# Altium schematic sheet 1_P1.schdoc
size 309 x 223 mm; Symbol: Sheet-Symbol_A4; Device: Sheet-Symbol_A4; Company: ChisBread/ChisFlash-Prometheus; Drawed: ChisBread; Reviewed: ChisBread; Version: 2; Page Size: A4; @Project Name: GBA烧录卡; @Page Count: 1; @Update Date: 2024-08-13; @Create Date: 2024-08-13; @Schematic Name: ChisFlash-Prometheus_1; @Page No: 1; @Page Name: P1
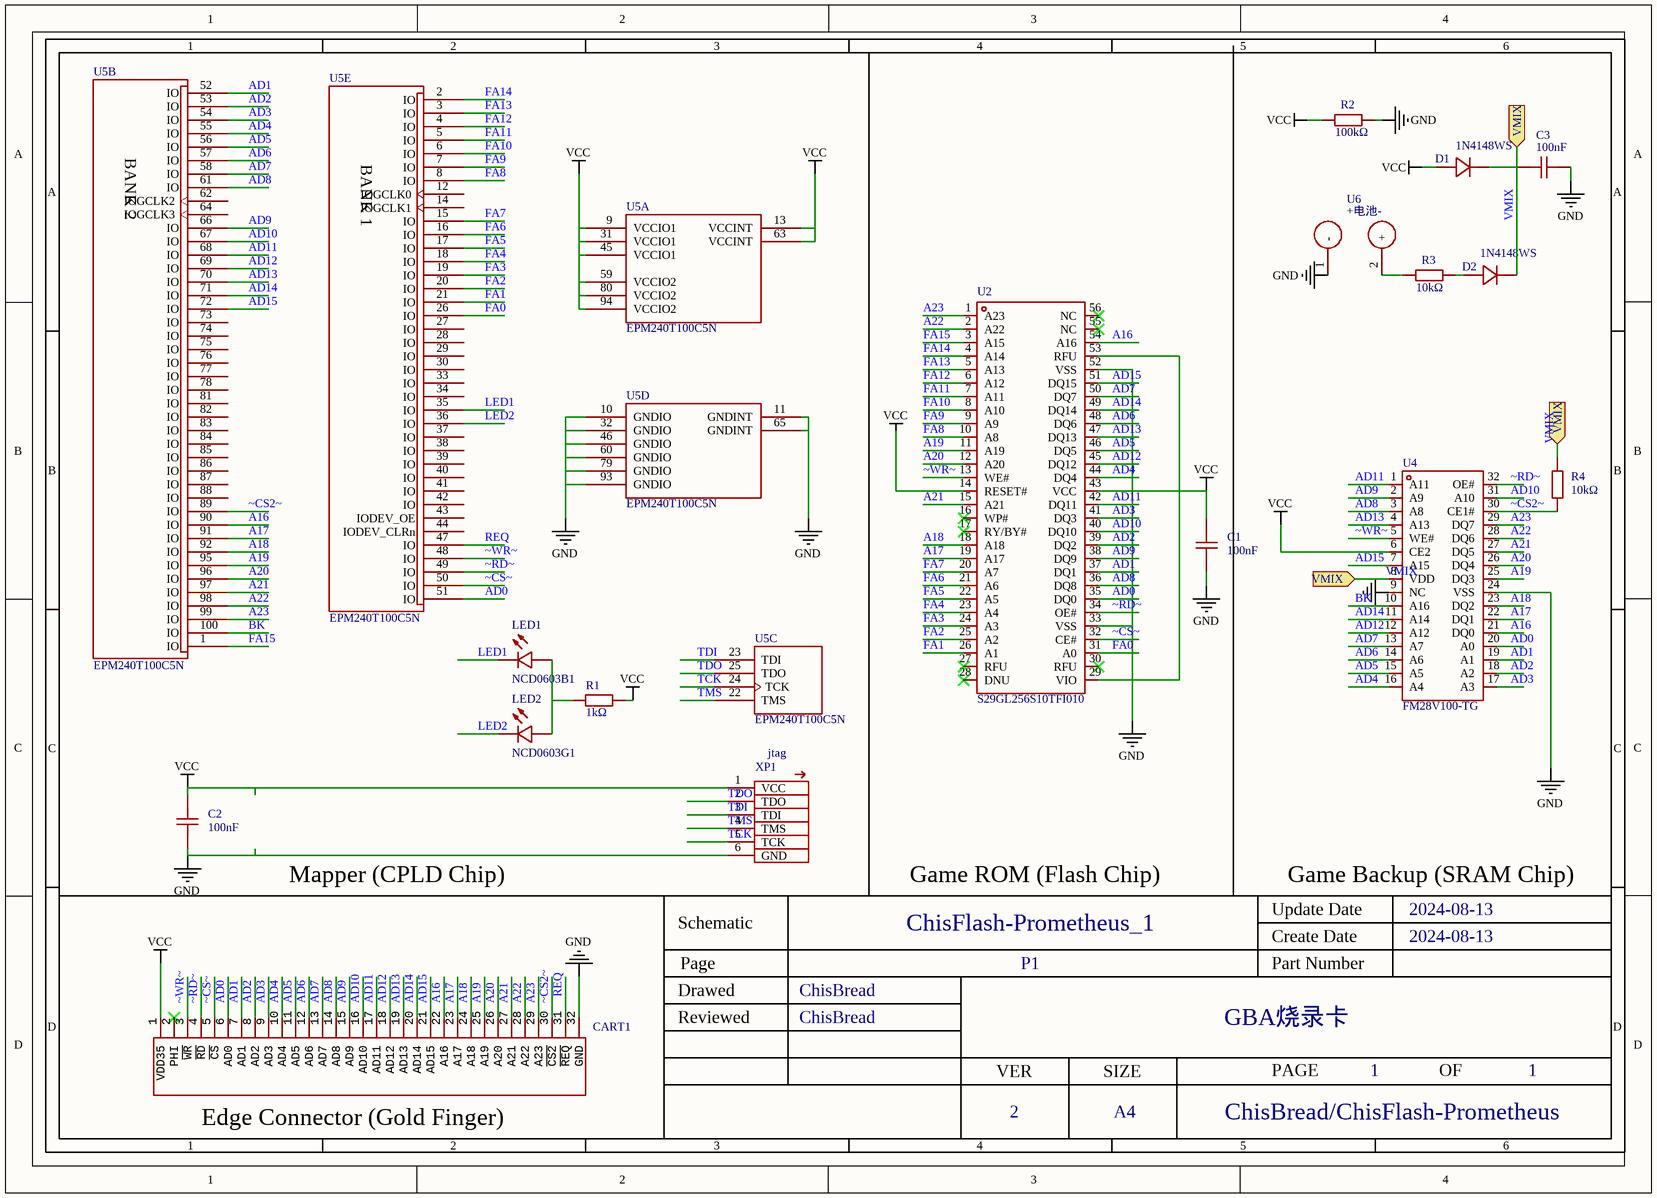
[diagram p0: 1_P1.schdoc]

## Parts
C1  100nF  [C0603]  (value not drawn)
C2  100nF  [C0603]  (value not drawn)
C3  100nF  [C0603]  (value not drawn)
CART1  GBACartridge  [GBACartridge]  (value not drawn)
D1  1N4148WS  [SOD-323_L1.8-W1.3-LS2.5-RD]  (value not drawn)
D2  1N4148WS  [SOD-323_L1.8-W1.3-LS2.5-RD]  (value not drawn)
LED1  NCD0603B1  [LED0603-RD]  (value not drawn)
LED2  NCD0603G1  [LED0603-RD]  (value not drawn)
R1  1kΩ  [R0603]  (value not drawn)
R2  100kΩ  [R0603]  (value not drawn)
R3  10kΩ  [R0603]  (value not drawn)
R4  10kΩ  [R0603]  (value not drawn)
U2  S29GL256S10TFI010  [TSOP-56_L18.4-W14.0-P0.50-LS20.0-TL]  (value not drawn)
U4  FM28V100-TG  [STSOP-32_L8.0-W11.8-P0.50-LS13.4-TL]  (value not drawn)
U5  EPM240T100C5N  [TQFP-100_L14.0-W14.0-P0.50-LS16.0-BL]  (value not drawn)  (parts A,B,C,D,E of 5)
U6  +电池-  [电池]  (value not drawn)
XP1  jtag  [HDR-TH_6P-P1.27-V-M-1]  (value not drawn)

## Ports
VMIX (in)

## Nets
GND: C1.1 C2.1 C3.2 CART1.32(GND) R2.2 U2.33(VSS) U2.52(VSS) U4.9(NC) U4.24(VSS) U5.10(GNDIO) U5.11(GNDINT) U5.32(GNDIO) U5.46(GNDIO) U5.60(GNDIO) U5.65(GNDINT) U5.79(GNDIO) U5.93(GNDIO) U6.1(-) XP1.6(GND)
VCC: C1.2 C2.2 CART1.1(VDD35) D1.2(A) R1.2 R2.1 U2.14(RESET#) U2.29(VIO) U2.43(VCC) U2.53(RFU) U4.6(CE2) U5.9(VCCIO1) U5.13(VCCINT) U5.31(VCCIO1) U5.45(VCCIO1) U5.59(VCCIO2) U5.63(VCCINT) U5.80(VCCIO2) U5.94(VCCIO2) XP1.1(VCC)
A16: CART1.22(A16) U2.54(A16) U4.21(DQ0) U5.90(IO)
A17: CART1.23(A17) U2.19(A17) U4.22(DQ1) U5.91(IO)
A18: CART1.24(A18) U2.18(A18) U4.23(DQ2) U5.92(IO)
A19: CART1.25(A19) U2.11(A19) U4.25(DQ3) U5.95(IO)
A20: CART1.26(A20) U2.12(A20) U4.26(DQ4) U5.96(IO)
A21: CART1.27(A21) U2.15(A21) U4.27(DQ5) U5.97(IO)
A22: CART1.28(A22) U2.2(A22) U4.28(DQ6) U5.98(IO)
A23: CART1.29(A23) U2.1(A23) U4.29(DQ7) U5.99(IO)
AD0: CART1.6(AD0) U2.35(DQ0) U4.20(A0) U5.51(IO)
AD1: CART1.7(AD1) U2.37(DQ1) U4.19(A1) U5.52(IO)
AD2: CART1.8(AD2) U2.39(DQ2) U4.18(A2) U5.53(IO)
AD3: CART1.9(AD3) U2.41(DQ3) U4.17(A3) U5.54(IO)
AD4: CART1.10(AD4) U2.44(DQ4) U4.16(A4) U5.55(IO)
AD5: CART1.11(AD5) U2.46(DQ5) U4.15(A5) U5.56(IO)
AD6: CART1.12(AD6) U2.48(DQ6) U4.14(A6) U5.57(IO)
AD7: CART1.13(AD7) U2.50(DQ7) U4.13(A7) U5.58(IO)
AD8: CART1.14(AD8) U2.36(DQ8) U4.3(A8) U5.61(IO)
AD9: CART1.15(AD9) U2.38(DQ9) U4.2(A9) U5.66(IO)
AD10: CART1.16(AD10) U2.40(DQ10) U4.31(A10) U5.67(IO)
AD11: CART1.17(AD11) U2.42(DQ11) U4.1(A11) U5.68(IO)
AD12: CART1.18(AD12) U2.45(DQ12) U4.12(A12) U5.69(IO)
AD13: CART1.19(AD13) U2.47(DQ13) U4.4(A13) U5.70(IO)
AD14: CART1.20(AD14) U2.49(DQ14) U4.11(A14) U5.71(IO)
AD15: CART1.21(AD15) U2.51(DQ15) U4.7(A15) U5.72(IO)
BK: U4.10(A16) U5.100(IO)
FA0: U2.31(A0) U5.26(IO)
FA1: U2.26(A1) U5.21(IO)
FA2: U2.25(A2) U5.20(IO)
FA3: U2.24(A3) U5.19(IO)
FA4: U2.23(A4) U5.18(IO)
FA5: U2.22(A5) U5.17(IO)
FA6: U2.21(A6) U5.16(IO)
FA7: U2.20(A7) U5.15(IO)
FA8: U2.10(A8) U5.8(IO)
FA9: U2.9(A9) U5.7(IO)
FA10: U2.8(A10) U5.6(IO)
FA11: U2.7(A11) U5.5(IO)
FA12: U2.6(A12) U5.4(IO)
FA13: U2.5(A13) U5.3(IO)
FA14: U2.4(A14) U5.2(IO)
FA15: U2.3(A15) U5.1(IO)
LED1: LED1.1(-) U5.35(IO)
LED2: LED2.1(K) U5.36(IO)
REQ: CART1.31(~{REQ}) U5.47(IO)
TCK: U5.24(TCK) XP1.5(TCK)
TDI: U5.23(TDI) XP1.3(TDI)
TDO: U5.25(TDO) XP1.2(TDO)
TMS: U5.22(TMS) XP1.4(TMS)
VMIX: C3.1 D1.1(C) D2.1(C) R4.2 U4.8(VDD) ; port VMIX
~CS2~: CART1.30(~{CS2}) R4.1 U4.30(CE1#) U5.89(IO)
~CS~: CART1.5(~{CS}) U2.32(CE#) U5.50(IO)
~RD~: CART1.4(~{RD}) U2.34(OE#) U4.32(OE#) U5.49(IO)
~WR~: CART1.3(~{WR}) U2.13(WE#) U4.5(WE#) U5.48(IO)
NetD2_2: D2.2(A) R3.2
NetLED1_2: LED1.2(+) LED2.2(A) R1.1
NetR3_1: R3.1 U6.2(+)

Not connected (* = marked no-connect by the designer): CART1 2(PHI)*; U2 16(WP#)* 17(RY/BY#)* 27(RFU)* 28(DNU)* 30(RFU)* 55(NC)* 56(NC)*; U5 12(IOGCLK0) 14(IOGCLK1) 27(IO) 28(IO) 29(IO) 30(IO) 33(IO) 34(IO) 37(IO) 38(IO) 39(IO) 40(IO) 41(IO) 42(IO) 43(IODEV_OE) 44(IODEV_CLRn) 62(IOGCLK2) 64(IOGCLK3) 73(IO) 74(IO) 75(IO) 76(IO) 77(IO) 78(IO) 81(IO) 82(IO) 83(IO) 84(IO) 85(IO) 86(IO) 87(IO) 88(IO)

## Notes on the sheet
- Mapper (CPLD Chip)
- Game ROM (Flash Chip)
- Game Backup (SRAM Chip)
- Edge Connector (Gold Finger)

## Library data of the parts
C1 C2 = CAP_0603: Symbol: CapAcitance; Convert to PCB: yes
C3 = CGA0603X7R104K500JT: 容值:100nF;精度:±10%;额定电压:50V;材质(温度系数):X7R;; Manufacturer: HRE(芯声); Add into BOM: yes; Tolerance: ±10%; Voltage Rated: 50V; Temperature Coefficient: X7R
CART1 = GBACartridge: GBA Cartridge; Convert to PCB: yes; Add into BOM: no
D1 D2 = 1N4148WS_C917117: 二极管配置:独立式;正向压降(Vf):1.25V@150mA;直流反向耐压(Vr):100V;平均整流电流(Io):300mA;功率:400mW;反向恢复时间(trr):8ns;; Manufacturer: JSMSEMI(杰盛微); Add into BOM: yes; Diode Configuration: 独立式; Reverse Voltage (Vr): 100V; Average Rectified Current (Io): 300mA; Power Dissipation: 400mW; Reverse Leakage Current: 1uA@75V; Reverse Recovery Time (trr): 8ns; Origin Footprint: SOD-123_L2.8-W1.8-LS3.7-RD
LED1 = NCD0603B1: 发光颜色:蓝色;正向电压(VF):2.6V~3.6V;功率:72mW;正向电流:10mA;主波长:463nm~475nm;透镜颜色:无色透明透镜;发光强度:80mcd~220mcd;发光角度:130°;工作温度:-30℃~+85℃;; Manufacturer: 国星光电; Symbol: FC-DA1608BK-470H10; Add into BOM: yes; Emitted Color: 蓝色; Power Dissipation: 72mW; Forward Current: 10mA; Lens Color: 无色透明透镜; Viewing Angle: 130°
LED2 = NCD0603G1: 发光颜色:翠绿色;正向电压(VF):2.6V~3.6V;功率:72mW;正向电流:10mA;主波长:515nm~530nm;透镜颜色:无色透明透镜;发光强度:330mcd~900mcd;发光角度:130°;工作温度:-30℃~+85℃;; Manufacturer: 国星光电; Symbol: FC-D1608UGK-520D10; Add into BOM: yes; Emitted Color: 翠绿色; Power Dissipation: 72mW; Forward Current: 10mA; Lens Color: 无色透明透镜; Viewing Angle: 130°
R1 = 0603WAF1001T5E: 电阻类型:厚膜电阻;阻值:1kΩ;精度:±1%;功率:100mW;最大工作电压:75V;温度系数:±100ppm/℃;; Manufacturer: UNI-ROYAL(厚声); Add into BOM: yes; Tolerance: ±1%; Power(Watts): 100mW; Overload Voltage (Max): 75V
R2 = 0603WAF1003T5E: 电阻类型:厚膜电阻;阻值:100kΩ;精度:±1%;功率:100mW;最大工作电压:75V;温度系数:±100ppm/℃;; Manufacturer: UNI-ROYAL(厚声); Add into BOM: yes; Tolerance: ±1%; Power(Watts): 100mW; Overload Voltage (Max): 75V; Resistance: 47K
R3 R4 = 0603WAF1002T5E: 电阻类型:厚膜电阻;阻值:10kΩ;精度:±1%;功率:100mW;最大工作电压:75V;温度系数:±100ppm/℃;; Manufacturer: UNI-ROYAL(厚声); Add into BOM: yes; Tolerance: ±1%; Power(Watts): 100mW; Overload Voltage (Max): 75V; Resistance: 47K
U2 = S29GL256S10TFI010: Manufacturer: SPANSION(飞索); Add into BOM: yes
U4 = FM28V100-TG: Manufacturer: CYPRESS(赛普拉斯); Symbol: FM28V100-TG_C2959453; Add into BOM: yes
U5 = EPM240T100C5N: 类型:其它PLD;逻辑门数量:-;逻辑单元数:-;逻辑阵列块数:240;; Manufacturer: Intel/Altera; Add into BOM: yes; Supply Voltage Range - VCCIO: 3.3V；2.5V; Logic Array Blocks: 240; Maximum Delay Time Tpd: 4.7ns; Relevance: []
U6 = +电池-: Add into BOM: yes
XP1 = jtag: Convert to PCB: yes; Add into BOM: no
